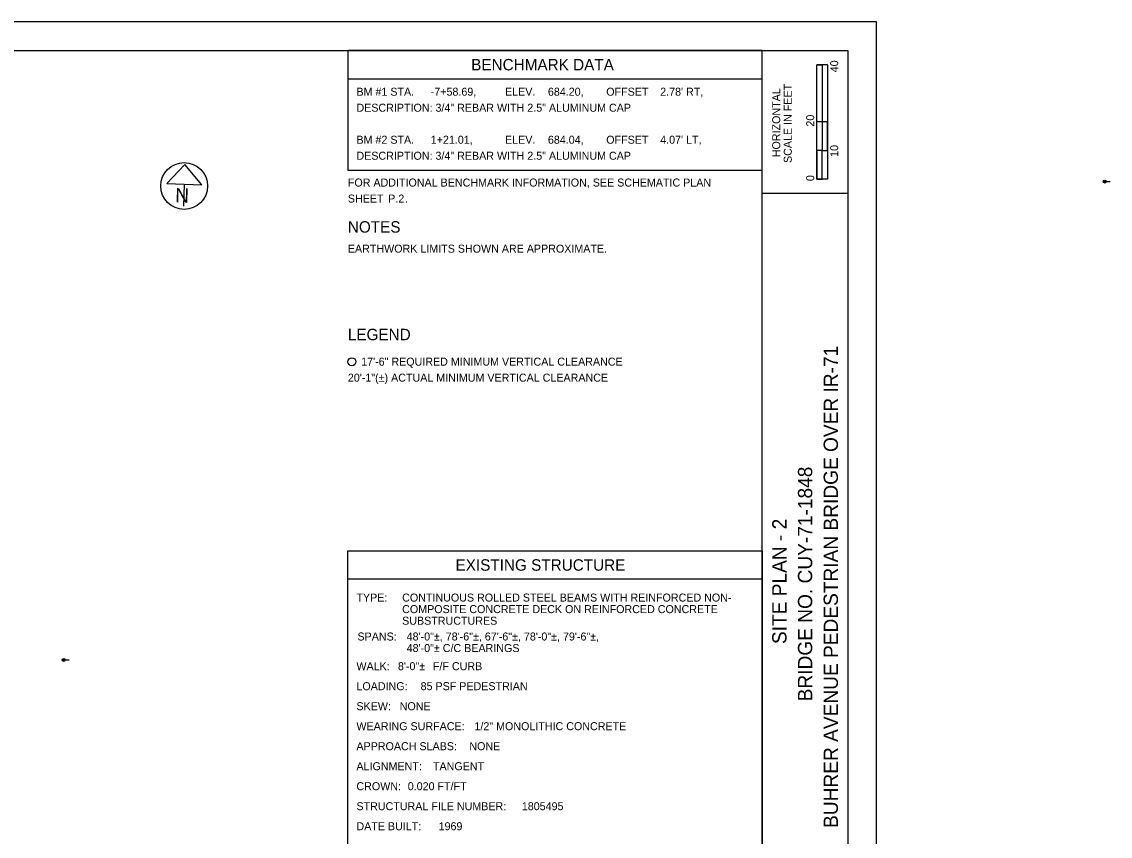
# Model space of a CAD drawing. Extents: x 39.5 to 77.6, y 9.5 to 31.5.
# Drawn here: x 58.53 to 77.57, y 17.25 to 31.5 of the extents above; entities that cross this region are included whole.
import ezdxf

# ---------------------------------------------------------------- set-up
doc = ezdxf.new("R2010")
doc.units = 0
for name, color, linetype in [('SH_Border', 7, 'Continuous'), ('SH_Cut_Line', 7, 'Continuous'), ('SH_Data', 7, 'Continuous'), ('SH_Masking', 7, 'Continuous'), ('SH_Named_Boundary', 7, 'Continuous'), ('SH_Text', 7, 'Continuous')]:
    doc.layers.add(name, color=color, linetype=linetype)

msp = doc.modelspace()

# ---------------------------------------------------------------- linework, layer by layer
at = {"layer": 'SH_Border'}
for p, q in [((71.481, 9.999), (71.481, 30.999)), ((71.481, 28.499), (72.981, 28.499))]:
    msp.add_line(p, q, dxfattribs=at)
msp.add_lwpolyline([(40.981, 30.999), (72.981, 30.999), (72.981, 9.999), (40.981, 9.999)], close=True, dxfattribs=at)
at = {"layer": 'SH_Cut_Line'}
msp.add_lwpolyline([(39.481, 9.499), (73.481, 9.499), (73.481, 31.499), (39.481, 31.499)], close=True, dxfattribs=at)
at = {"layer": 'SH_Data'}
for p, q in [((72.437, 29.749), (72.437, 30.749)), ((72.437, 30.749), (72.531, 30.749)), ((72.437, 28.749), (72.437, 30.749)), ((72.625, 30.749), (72.437, 30.749)), ((72.531, 30.749), (72.532, 30.749)), ((72.532, 30.749), (72.532, 29.749)), ((72.625, 30.749), (72.625, 28.749)), ((64.231, 30.499), (71.481, 30.499)), ((72.532, 29.749), (72.437, 29.749)), ((72.624, 29.749), (72.531, 29.749)), ((72.531, 29.749), (72.531, 29.249)), ((72.624, 29.249), (72.624, 29.749)), ((72.531, 29.249), (72.437, 29.249)), ((72.437, 29.249), (72.437, 28.749)), ((72.531, 29.249), (72.624, 29.249)), ((72.531, 28.749), (72.531, 29.249)), ((72.625, 28.749), (72.437, 28.749)), ((72.437, 28.749), (72.531, 28.749)), ((71.481, 21.747), (64.231, 21.747))]:
    msp.add_line(p, q, dxfattribs=at)
for points in [[(71.481, 30.999), (64.231, 30.999), (64.231, 28.905), (71.481, 28.905)], [(64.231, 22.247), (71.481, 22.247), (71.481, 16.633), (64.231, 16.633)]]:
    msp.add_lwpolyline(points, close=True, dxfattribs=at)
msp.add_circle((64.301, 25.553), 0.07, dxfattribs=at)
at = {"layer": 'SH_Masking'}
msp.add_circle((61.367, 28.627), 0.41, dxfattribs=at)
at = {"layer": 'SH_Named_Boundary'}
for p, q in [((77.448, 28.704), (77.5, 28.704)), ((77.474, 28.704), (77.57, 28.704)), ((59.233, 20.336), (59.285, 20.336)), ((59.259, 20.336), (59.356, 20.336))]:
    msp.add_line(p, q, dxfattribs=at)
for centre in [(77.474, 28.704), (59.259, 20.336)]:
    msp.add_circle(centre, 0.026, dxfattribs=at)
at = {"layer": 'SH_Text'}
for p, q in [((61.379, 29), (61.061, 28.669)), ((61.676, 28.65), (61.379, 29)), ((61.061, 28.669), (61.676, 28.65)), ((61.368, 28.659), (61.356, 28.273))]:
    msp.add_line(p, q, dxfattribs=at)
msp.add_circle((61.367, 28.627), 0.41, dxfattribs=at)

# ---------------------------------------------------------------- texts
at = {"layer": 'SH_Data'}
for s, height, p in [('BENCHMARK DATA', 0.2, (66.389, 30.649)), ('BM #1 STA.', 0.14, (64.381, 30.206)), ('-7+58.69,', 0.14, (65.681, 30.206)), ('ELEV.', 0.14, (66.981, 30.206)), ('684.20,', 0.14, (67.731, 30.206)), ('OFFSET', 0.14, (68.752, 30.206)), ("2.78' RT,", 0.14, (69.696, 30.206)), ('DESCRIPTION: 3/4" REBAR WITH 2.5" ALUMINUM CAP ', 0.14, (64.381, 29.926)), ('BM #2 STA.', 0.14, (64.381, 29.366)), ('1+21.01,', 0.14, (65.681, 29.366)), ('ELEV.', 0.14, (66.981, 29.366)), ('684.04,', 0.14, (67.731, 29.366)), ('OFFSET', 0.14, (68.752, 29.366)), ("4.07' LT,", 0.14, (69.696, 29.366)), ('DESCRIPTION: 3/4" REBAR WITH 2.5" ALUMINUM CAP ', 0.14, (64.381, 29.086)), ('FOR ADDITIONAL BENCHMARK INFORMATION, SEE SCHEMATIC PLAN', 0.14, (64.231, 28.617)), ('SHEET ', 0.14, (64.231, 28.337)), ('P.2', 0.14, (64.937, 28.337)), ('.', 0.14, (65.231, 28.337)), ('NOTES', 0.2, (64.231, 27.811)), ('EARTHWORK LIMITS SHOWN ARE APPROXIMATE.  ', 0.14, (64.231, 27.461)), ('LEGEND', 0.2, (64.231, 25.929)), ('EXISTING STRUCTURE', 0.2, (66.115, 21.897)), ('TYPE:', 0.14, (64.381, 21.357)), ('CONTINUOUS ROLLED STEEL BEAMS WITH REINFORCED NON-', 0.14, (65.181, 21.357)), ('COMPOSITE CONCRETE DECK ON REINFORCED CONCRETE ', 0.14, (65.181, 21.155)), ('SUBSTRUCTURES', 0.14, (65.181, 20.952)), ('SPANS:', 0.14, (64.399, 20.676)), ('48\'-0"±, 78\'-6"±, 67\'-6"±, 78\'-0"±, 79\'-6"±, ', 0.14, (65.26, 20.676)), ('48\'-0"± C/C BEARINGS', 0.14, (65.26, 20.474)), ('WALK:', 0.14, (64.381, 20.157)), ('8\'-0"±', 0.14, (65.107, 20.157)), ('F/F CURB', 0.14, (65.719, 20.157)), ('LOADING:', 0.14, (64.381, 19.807)), ('85 PSF PEDESTRIAN', 0.14, (65.504, 19.807)), ('SKEW:', 0.14, (64.381, 19.457)), ('NONE', 0.14, (65.138, 19.457)), ('WEARING SURFACE:', 0.14, (64.381, 19.107)), ('1/2" MONOLITHIC CONCRETE', 0.14, (66.446, 19.107)), ('APPROACH SLABS:', 0.14, (64.381, 18.757)), ('NONE', 0.14, (66.357, 18.757)), ('ALIGNMENT:', 0.14, (64.381, 18.407)), ('TANGENT', 0.14, (65.72, 18.407)), ('CROWN:', 0.14, (64.381, 18.057)), ('0.020 FT/FT', 0.14, (65.279, 18.057)), ('STRUCTURAL FILE NUMBER:', 0.14, (64.381, 17.707)), ('1805495', 0.14, (67.275, 17.707)), ('DATE BUILT:', 0.14, (64.381, 17.357)), ('1969', 0.14, (65.819, 17.357))]:
    msp.add_text(s, height=height, dxfattribs=at).set_placement(p)
for s, height, rotation, p in [('40', 0.14, 90, (72.811, 30.616)), ('HORIZONTAL', 0.14, 90, (71.796, 29.13)), ('SCALE IN FEET', 0.14, 90, (71.998, 29.029)), ('20', 0.14, 90, (72.391, 29.666)), ('10', 0.14, 90, (72.811, 29.136)), ('0', 0.14, 90, (72.391, 28.713)), ('BUHRER AVENUE PEDESTRIAN BRIDGE OVER IR-71', 0.25, 90, (72.806, 17.398)), ('17\'-6" REQUIRED MINIMUM VERTICAL CLEARANCE', 0.14, 0, (64.464, 25.484)), ('20\'-1"(±) ACTUAL MINIMUM VERTICAL CLEARANCE', 0.14, 0, (64.231, 25.204)), ('BRIDGE NO. CUY-71-1848', 0.25, 90, (72.356, 19.612)), ('SITE PLAN - 2', 0.25, 90, (71.906, 20.614))]:
    msp.add_text(s, height=height, rotation=rotation, dxfattribs=at).set_placement(p)
at = {"layer": 'SH_Named_Boundary'}
for s, p in [('P.19', (77.469, 28.694)), ('1', (77.473, 28.711)), ('105793_SFN_1805495_SP002', (77.506, 28.711)), ('1:20', (77.506, 28.694)), ('P.19', (59.255, 20.327)), ('2', (59.258, 20.343)), ('105793_SFN_1805495_SP004', (59.292, 20.343)), ('1:20', (59.292, 20.327))]:
    msp.add_text(s, height=0.00328, dxfattribs=at).set_placement(p)
at = {"layer": 'SH_Text'}
msp.add_text('N', height=0.25, rotation=358.2375, dxfattribs=at).set_placement((61.207, 28.34))

doc.saveas('drawing.dxf')
